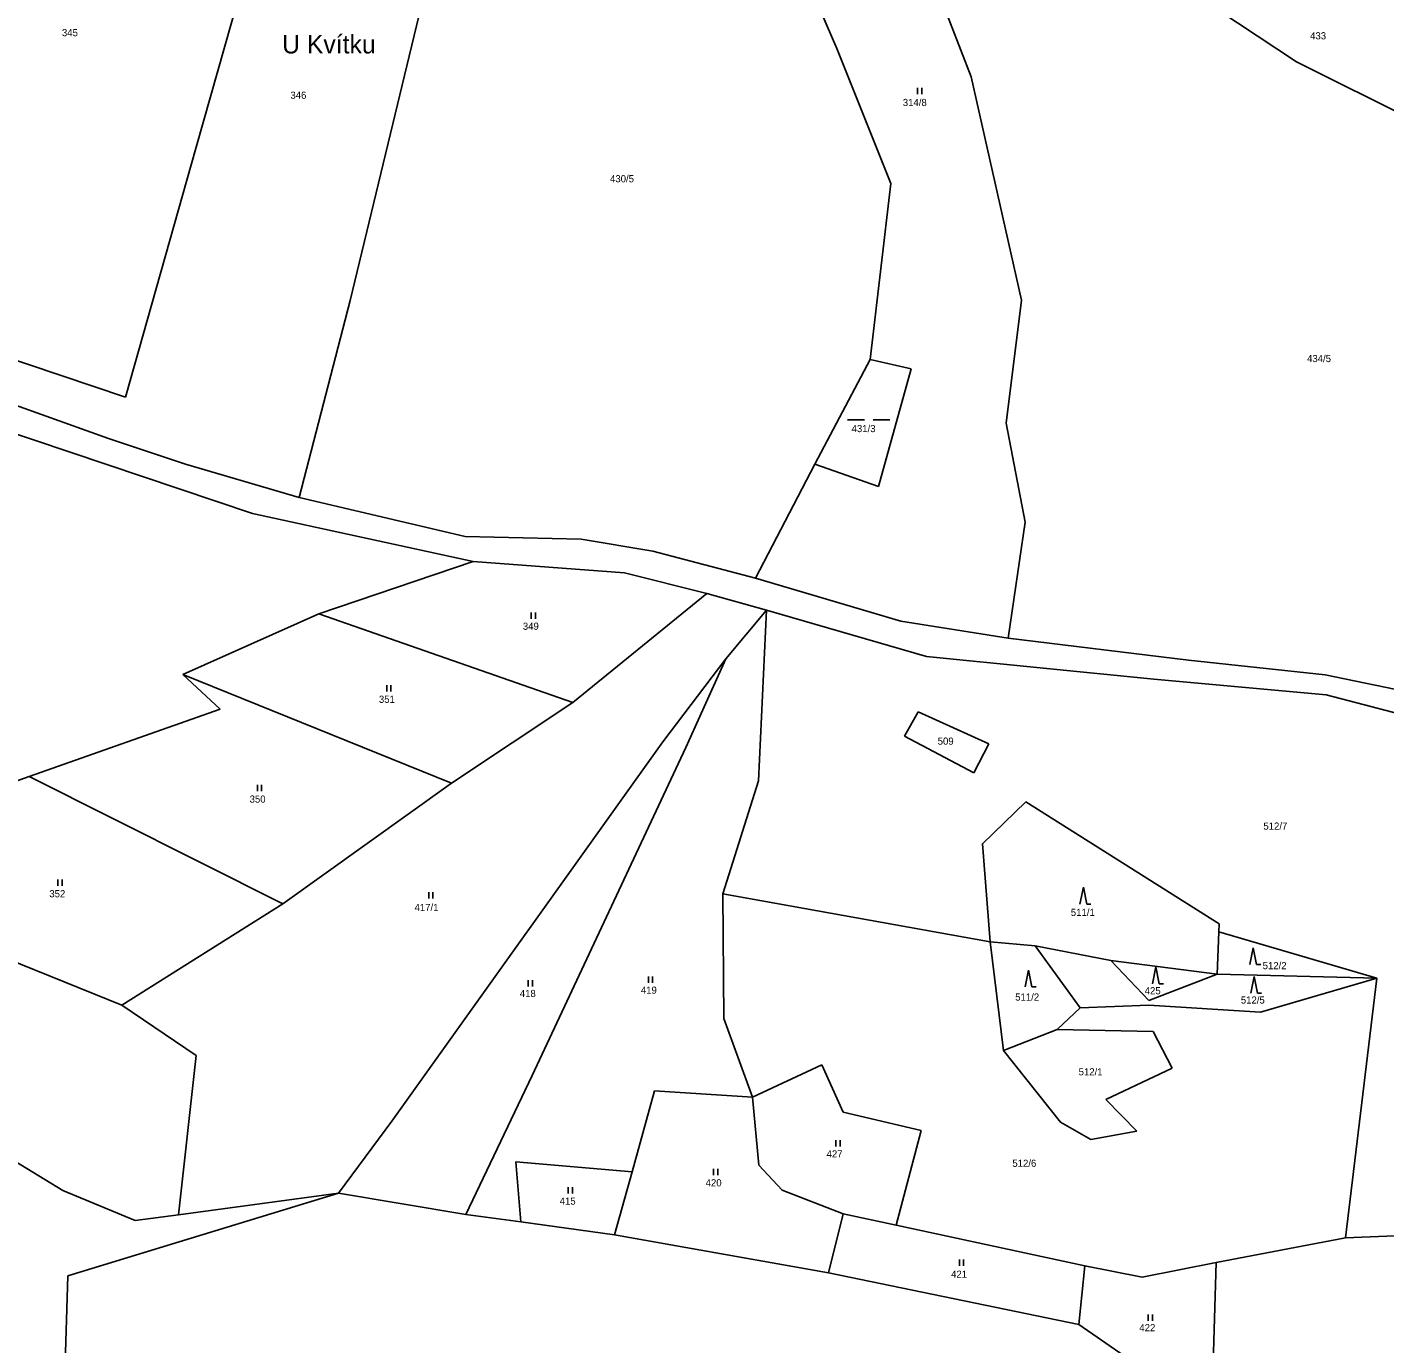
# Model space of a CAD drawing. Extents: x -794421 to -792735, y -1117671 to -1115559.
# Drawn here: x -794140.7 to -793818.1, y -1117103.6 to -1116790.7 of the extents above; entities that cross this region are included whole.
import ezdxf

# ---------------------------------------------------------------- set-up
doc = ezdxf.new("R2010")
doc.units = 0
for name, color, linetype in [('Vrstva 1', 7, 'Continuous'), ('Vrstva 14', 7, 'Continuous'), ('Vrstva 23', 7, 'Continuous'), ('Vrstva 39', 7, 'Continuous')]:
    doc.layers.add(name, color=color, linetype=linetype)

msp = doc.modelspace()

# ---------------------------------------------------------------- linework, layer by layer
at = {"layer": 'Vrstva 1'}
for p, q in [((-794100.53, -1116819.2), (-794073.14, -1116722.69)), ((-794032.73, -1116726.38), (-794063.93, -1116855.67)), ((-793940.58, -1116740.03), (-793916.37, -1116802.53)), ((-793948.27, -1116795.8), (-793962.04, -1116763.8)), ((-793839.07, -1116798.91), (-793876.78, -1116773.96)), ((-793935.42, -1116827.84), (-793948.27, -1116795.8)), ((-793791.34, -1116822.79), (-793839.07, -1116798.91)), ((-793916.37, -1116802.53), (-793904.38, -1116855.6)), ((-794117.35, -1116878.62), (-794100.53, -1116819.2)), ((-793940.34, -1116869.71), (-793935.42, -1116827.84)), ((-794177.62, -1116858.32), (-794117.35, -1116878.62)), ((-794063.93, -1116855.67), (-794076.05, -1116902.45)), ((-793904.38, -1116855.6), (-793908.06, -1116884.82)), ((-794180.61, -1116867.3), (-794121.37, -1116888.44)), ((-793953.51, -1116894.59), (-793940.34, -1116869.71)), ((-793940.34, -1116869.71), (-793930.64, -1116871.88)), ((-793930.64, -1116871.88), (-793938.35, -1116899.88)), ((-794176.47, -1116876.29), (-794087.13, -1116906.27)), ((-793908.06, -1116884.82), (-793903.52, -1116908.3)), ((-794121.37, -1116888.44), (-794103.09, -1116894.59)), ((-794103.09, -1116894.59), (-794076.05, -1116902.45)), ((-793967.65, -1116921.67), (-793953.51, -1116894.59)), ((-793938.35, -1116899.88), (-793953.51, -1116894.59)), ((-794076.05, -1116902.45), (-794036.61, -1116911.78)), ((-794087.13, -1116906.27), (-794034.7, -1116917.66)), ((-793903.52, -1116908.3), (-793907.61, -1116935.91)), ((-794036.61, -1116911.78), (-794009.04, -1116912.34)), ((-794009.04, -1116912.34), (-793992.02, -1116915.24)), ((-793992.02, -1116915.24), (-793967.65, -1116921.67)), ((-794071.4, -1116930.13), (-794034.7, -1116917.66)), ((-794034.7, -1116917.66), (-793998.72, -1116920.39)), ((-793998.72, -1116920.39), (-793979.2, -1116925.32)), ((-793933.1, -1116931.83), (-793967.65, -1116921.67)), ((-794011.06, -1116951.18), (-793979.2, -1116925.32)), ((-793979.2, -1116925.32), (-793965, -1116929.23)), ((-793965, -1116929.23), (-793974.64, -1116940.78)), ((-793965, -1116929.23), (-793966.87, -1116969.78)), ((-793926.97, -1116940.24), (-793965, -1116929.23)), ((-794103.73, -1116944.52), (-794071.4, -1116930.13)), ((-794071.4, -1116930.13), (-794011.06, -1116951.18)), ((-793907.61, -1116935.91), (-793933.1, -1116931.83)), ((-793907.61, -1116935.91), (-793864.72, -1116941.09)), ((-793989.64, -1116960.55), (-793974.64, -1116940.78)), ((-793974.64, -1116940.78), (-793984.21, -1116961.88)), ((-793872.95, -1116945.62), (-793926.97, -1116940.24)), ((-793864.72, -1116941.09), (-793832.28, -1116944.58)), ((-794094.83, -1116952.74), (-794103.73, -1116944.52)), ((-794039.83, -1116970.34), (-794103.73, -1116944.52)), ((-793832, -1116949.35), (-793872.95, -1116945.62)), ((-793832.28, -1116944.58), (-793800.98, -1116951.05)), ((-794011.06, -1116951.18), (-794039.83, -1116970.34)), ((-793809.56, -1116955.26), (-793832, -1116949.35)), ((-794140.21, -1116968.76), (-794094.83, -1116952.74)), ((-793932.23, -1116959.15), (-793928.95, -1116953.4)), ((-793928.95, -1116953.4), (-793912.17, -1116961.03)), ((-794054.03, -1117050.71), (-793989.64, -1116960.55)), ((-793984.21, -1116961.88), (-794020.65, -1117039.83)), ((-793915.77, -1116967.9), (-793932.23, -1116959.15)), ((-793912.17, -1116961.03), (-793915.77, -1116967.9)), ((-794146.84, -1116971.14), (-794140.21, -1116968.76)), ((-794079.94, -1116999.05), (-794140.21, -1116968.76)), ((-794079.94, -1116999.05), (-794039.83, -1116970.34)), ((-793966.87, -1116969.78), (-793975.37, -1116996.64)), ((-793913.7, -1116984.8), (-793903.35, -1116974.83)), ((-793903.35, -1116974.83), (-793857.45, -1117003.75)), ((-793911.82, -1117008.06), (-793913.7, -1116984.8)), ((-793975.37, -1116996.64), (-793975.12, -1117026.27)), ((-793975.37, -1116996.64), (-793911.82, -1117008.06)), ((-794118.17, -1117023.08), (-794079.94, -1116999.05)), ((-793857.45, -1117003.75), (-793857.52, -1117005.65)), ((-793857.52, -1117005.65), (-793857.92, -1117015.75)), ((-793819.96, -1117016.73), (-793857.52, -1117005.65)), ((-793911.82, -1117008.06), (-793901.14, -1117009)), ((-793908.67, -1117033.88), (-793911.82, -1117008.06)), ((-793901.14, -1117009), (-793890.43, -1117023.76)), ((-793883.15, -1117012.5), (-793901.14, -1117009)), ((-794145.61, -1117012.04), (-794118.17, -1117023.08)), ((-793883.15, -1117012.5), (-793857.92, -1117015.75)), ((-793874.12, -1117022), (-793883.15, -1117012.5)), ((-793857.92, -1117015.75), (-793874.12, -1117022)), ((-793857.92, -1117015.75), (-793819.96, -1117016.73)), ((-793847.64, -1117024.74), (-793819.96, -1117016.73)), ((-793819.96, -1117016.73), (-793827.45, -1117078.43)), ((-794118.17, -1117023.08), (-794100.53, -1117035.1)), ((-793874.13, -1117023.12), (-793890.43, -1117023.76)), ((-793847.64, -1117024.74), (-793874.13, -1117023.12)), ((-793975.12, -1117026.27), (-793968.36, -1117044.98)), ((-793890.43, -1117023.76), (-793895.94, -1117028.87)), ((-793895.94, -1117028.87), (-793908.67, -1117033.88)), ((-793895.94, -1117028.87), (-793873.1, -1117029.36)), ((-793873.1, -1117029.36), (-793868.63, -1117038.05)), ((-794100.53, -1117035.1), (-794104.73, -1117072.96)), ((-793895.14, -1117050.88), (-793908.67, -1117033.88)), ((-793968.36, -1117044.98), (-793951.86, -1117037.32)), ((-793951.86, -1117037.32), (-793946.81, -1117048.55)), ((-793868.63, -1117038.05), (-793884.33, -1117045.55)), ((-794020.65, -1117039.83), (-794036.43, -1117072.82)), ((-793996.95, -1117062.74), (-793991.6, -1117043.49)), ((-793991.6, -1117043.49), (-793968.36, -1117044.98)), ((-793968.36, -1117044.98), (-793966.81, -1117061.17)), ((-793884.33, -1117045.55), (-793877.03, -1117053.03)), ((-793946.81, -1117048.55), (-793928.27, -1117052.91)), ((-794066.7, -1117067.79), (-794054.03, -1117050.71)), ((-793887.9, -1117055), (-793895.14, -1117050.88)), ((-794154.29, -1117053.65), (-794132.18, -1117067.16)), ((-793928.27, -1117052.91), (-793934.16, -1117075.39)), ((-793877.03, -1117053.03), (-793887.9, -1117055)), ((-794023.37, -1117074.61), (-794024.55, -1117060.38)), ((-794024.55, -1117060.38), (-793996.95, -1117062.74)), ((-793966.81, -1117061.17), (-793961.27, -1117067.09)), ((-794001.09, -1117077.66), (-793996.95, -1117062.74)), ((-794132.18, -1117067.16), (-794115.01, -1117074.27)), ((-794066.7, -1117067.79), (-794131, -1117087.43)), ((-794104.73, -1117072.96), (-794066.7, -1117067.79)), ((-794066.7, -1117067.79), (-794036.43, -1117072.82)), ((-793961.27, -1117067.09), (-793946.77, -1117072.68)), ((-794115.01, -1117074.27), (-794104.73, -1117072.96)), ((-794036.43, -1117072.82), (-794023.37, -1117074.61)), ((-794023.37, -1117074.61), (-794001.09, -1117077.66)), ((-793950.23, -1117086.71), (-793946.77, -1117072.68)), ((-793946.77, -1117072.68), (-793934.16, -1117075.39)), ((-794001.09, -1117077.66), (-793950.23, -1117086.71)), ((-793934.16, -1117075.39), (-793889.38, -1117085.03)), ((-793827.45, -1117078.43), (-793813.68, -1117077.82)), ((-793858.18, -1117084.24), (-793827.45, -1117078.43)), ((-793875.72, -1117087.73), (-793858.18, -1117084.24)), ((-793858.18, -1117084.24), (-793859.21, -1117120.82)), ((-794131, -1117087.43), (-794133.24, -1117157.84)), ((-793890.76, -1117098.96), (-793950.23, -1117086.71)), ((-793889.38, -1117085.03), (-793890.76, -1117098.96)), ((-793889.38, -1117085.03), (-793875.72, -1117087.73)), ((-793859.21, -1117120.82), (-793890.76, -1117098.96))]:
    msp.add_line(p, q, dxfattribs=at)
at = {"layer": 'Vrstva 23'}
for p, q in [((-793929.1, -1116806.65), (-793929.1, -1116805.15)), ((-793928.1, -1116805.15), (-793928.1, -1116806.65)), ((-793945.715, -1116884.01), (-793941.695, -1116884.01)), ((-793939.685, -1116884.01), (-793935.665, -1116884.01)), ((-794020.93, -1116931.31), (-794020.93, -1116929.81)), ((-794019.93, -1116929.81), (-794019.93, -1116931.31)), ((-794055.24, -1116948.57), (-794055.24, -1116947.07)), ((-794054.24, -1116947.07), (-794054.24, -1116948.57)), ((-794085.99, -1116972.26), (-794085.99, -1116970.76)), ((-794084.99, -1116970.76), (-794084.99, -1116972.26)), ((-794133.37, -1116994.77), (-794133.37, -1116993.27)), ((-794132.37, -1116993.27), (-794132.37, -1116994.77)), ((-794045.28, -1116997.75), (-794045.28, -1116996.25)), ((-794044.28, -1116996.25), (-794044.28, -1116997.75)), ((-793890.51, -1116999.09), (-793889.71, -1116995.09)), ((-793889.71, -1116995.09), (-793888.91, -1116999.09)), ((-793888.91, -1116999.09), (-793887.91, -1116999.09)), ((-793850.16, -1117013.45), (-793849.36, -1117009.45)), ((-793849.36, -1117009.45), (-793848.56, -1117013.45)), ((-793848.56, -1117013.45), (-793847.56, -1117013.45)), ((-793993.08, -1117017.81), (-793993.08, -1117016.31)), ((-793992.08, -1117016.31), (-793992.08, -1117017.81)), ((-793903.53, -1117018.79), (-793902.73, -1117014.79)), ((-793902.73, -1117014.79), (-793901.93, -1117018.79)), ((-793873.28, -1117018.01), (-793872.48, -1117014.01)), ((-793872.48, -1117014.01), (-793871.68, -1117018.01)), ((-793849.94, -1117020.3), (-793849.14, -1117016.3)), ((-793849.14, -1117016.3), (-793848.34, -1117020.3)), ((-794021.63, -1117018.67), (-794021.63, -1117017.17)), ((-794020.63, -1117017.17), (-794020.63, -1117018.67)), ((-793901.93, -1117018.79), (-793900.93, -1117018.79)), ((-793871.68, -1117018.01), (-793870.68, -1117018.01)), ((-793848.34, -1117020.3), (-793847.34, -1117020.3)), ((-793948.53, -1117056.68), (-793948.53, -1117055.18)), ((-793947.53, -1117055.18), (-793947.53, -1117056.68)), ((-793977.57, -1117063.53), (-793977.57, -1117062.03)), ((-793976.57, -1117062.03), (-793976.57, -1117063.53)), ((-794012.11, -1117067.88), (-794012.11, -1117066.38)), ((-794011.11, -1117066.38), (-794011.11, -1117067.88)), ((-793919.17, -1117085.03), (-793919.17, -1117083.53)), ((-793918.17, -1117083.53), (-793918.17, -1117085.03)), ((-793874.31, -1117098.12), (-793874.31, -1117096.62)), ((-793873.31, -1117096.62), (-793873.31, -1117098.12))]:
    msp.add_line(p, q, dxfattribs=at)

# ---------------------------------------------------------------- texts
at = {"layer": 'Vrstva 14'}
for s, p in [('345', (-794132.429, -1116792.86)), ('433', (-793835.813, -1116793.6)), ('346', (-794078.133, -1116807.72)), ('314/8', (-793932.609, -1116809.45)), ('430/5', (-794002.181, -1116827.57)), ('434/5', (-793836.548, -1116870.3)), ('431/3', (-793944.779, -1116886.94)), ('349', (-794022.903, -1116933.91)), ('351', (-794057.106, -1116951.27)), ('509', (-793924.322, -1116961.22)), ('350', (-794087.832, -1116974.99)), ('512/7', (-793846.926, -1116981.41)), ('352', (-794135.423, -1116997.48)), ('417/1', (-794048.639, -1117000.74)), ('511/1', (-793892.686, -1117001.91)), ('512/2', (-793847.099, -1117014.56)), ('418', (-794023.626, -1117021.18)), ('419', (-793994.856, -1117020.4)), ('425', (-793875.129, -1117020.53)), ('511/2', (-793905.903, -1117022.03)), ('512/5', (-793852.286, -1117022.73)), ('512/1', (-793890.833, -1117039.8)), ('427', (-793950.729, -1117059.31)), ('512/6', (-793906.579, -1117061.53)), ('420', (-793979.462, -1117066.17)), ('415', (-794014.152, -1117070.52)), ('421', (-793921.136, -1117087.89)), ('422', (-793876.402, -1117100.6))]:
    msp.add_text(s, height=1.7, dxfattribs=at).set_placement(p)
at = {"layer": 'Vrstva 39'}
msp.add_text('U Kvítku', height=4.4, dxfattribs=at).set_placement((-794080.1, -1116796.95))

doc.saveas('drawing.dxf')
